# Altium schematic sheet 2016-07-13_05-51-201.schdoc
size 307 x 144 mm; SheetNumber: 1; SheetTotal: 1
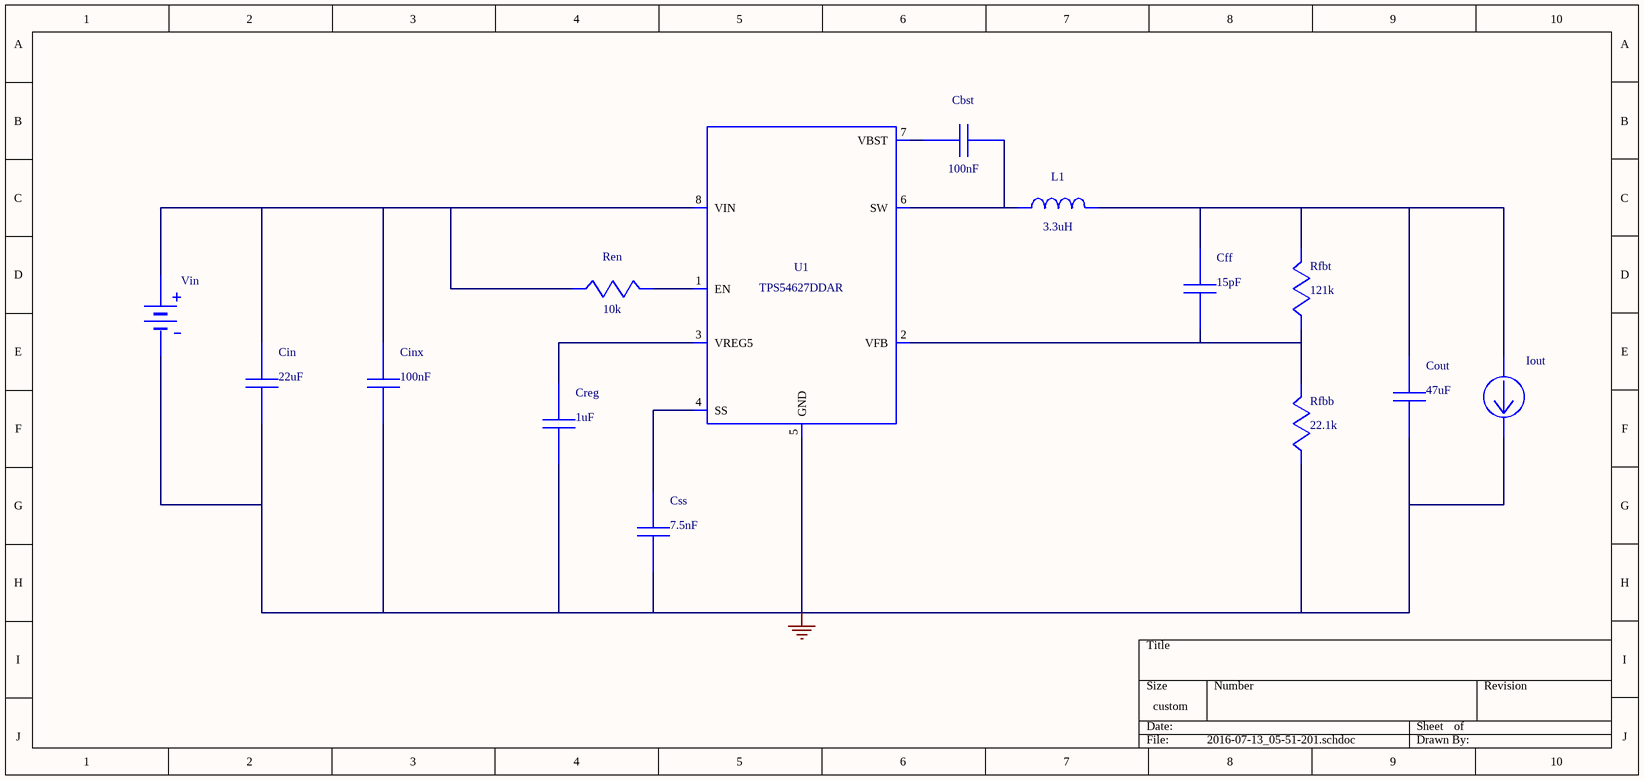
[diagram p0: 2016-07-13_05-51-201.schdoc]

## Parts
Cbst  value 100nF  (hidden comment: 06033C104KAT2A)
Cff  value 15pF  (hidden comment: C0603C150M8GACTU)
Cin  value 22uF  (hidden comment: GRM32ER61E226KE15L)
Cinx  value 100nF  (hidden comment: 06033C104KAT2A)
Cout  value 47uF  (hidden comment: GRM31CR61A476KE15L)
Creg  value 1uF  (hidden comment: GRM188R61A105KA61D)
Css  value 7.5nF  (hidden comment: GRM2195C1H752JA01D)
Iout  WB_CURRENT_LOAD  (value not drawn)
L1  value 3.3uH  (hidden comment: SRN6045-3R3Y)
Ren  value 10k  (hidden comment: CRCW040210K0FKED)
Rfbb  value 22.1k  (hidden comment: CRCW040222K1FKED)
Rfbt  value 121k  (hidden comment: CRCW0402121KFKED)
U1  TPS54627DDA  (value not drawn)
Vin  WB_BATTERY  (value not drawn)

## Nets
0: Cin.2 Cinx.2 Cout.2 Creg.2 Css.2 Iout.2(-) Rfbb.2 U1.5(GND) U1.9(ETPAD) Vin.2(-)
NetCbst_1: Cbst.1 U1.7(VBST)
NetCbst_2: Cbst.2 L1.1 U1.6(SW)
NetCff_1: Cff.1 Cout.1 Iout.1(+) L1.2 Rfbt.1
NetCff_2: Cff.2 Rfbb.1 Rfbt.2 U1.2(VFB)
NetCin_1: Cin.1 Cinx.1 Ren.2 U1.8(VIN) Vin.1(+)
NetCreg_1: Creg.1 U1.3(VREG5)
NetCss_1: Css.1 U1.4(SS)
NetRen_1: Ren.1 U1.1(EN)

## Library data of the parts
Cbst Cinx = 06033C104KAT2A: Manufacturer Name: AVX
Cff = C0603C150M8GACTU: Manufacturer Name: Kemet
Cin = GRM32ER61E226KE15L: GRM32ER61E226KE1; Manufacturer Name: MuRata
Cout = GRM31CR61A476KE15L: GRM31CR61A476KE1; Manufacturer Name: MuRata
Creg = GRM188R61A105KA61D: GRM188R61A105KA6; Manufacturer Name: MuRata
Css = GRM2195C1H752JA01D: GRM2195C1H752JA0; Manufacturer Name: MuRata
L1 = SRN6045-3R3Y: Manufacturer Name: Bourns
Ren = CRCW040210K0FKED: Manufacturer Name: Vishay-Dale
Rfbb = CRCW040222K1FKED: Manufacturer Name: Vishay-Dale
Rfbt = CRCW0402121KFKED: Manufacturer Name: Vishay-Dale
U1 = TPS54627DDA: TPS54627DDAR; Manufacturer Name: Texas Instruments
